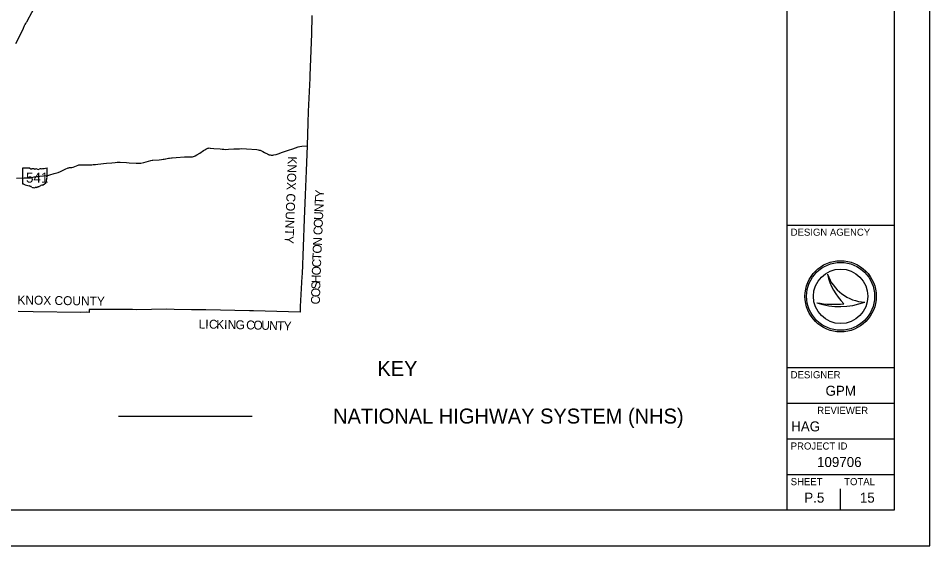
# Model space of a CAD drawing. Extents: x 1851937 to 2123937, y 789467 to 965467.
# Drawn here: x 2021685 to 2123937, y 789467 to 848684 of the extents above; entities that cross this region are included whole.
import ezdxf

# ---------------------------------------------------------------- set-up
doc = ezdxf.new("R2010")
doc.units = 0
for name, color, linetype in [('GM_X_County', 7, 'Continuous'), ('GM_X_County_Text', 7, 'Continuous'), ('GM_X_State_Route', 7, 'Continuous'), ('GM_X_State_Shield', 7, 'Continuous'), ('GM_X_US_Route', 7, 'Continuous'), ('SH_Border', 7, 'Continuous'), ('SH_Cut_Line', 7, 'Continuous'), ('SH_Data', 7, 'Continuous'), ('UT_P_Electric', 7, 'Continuous')]:
    doc.layers.add(name, color=color, linetype=linetype)

msp = doc.modelspace()

# ---------------------------------------------------------------- linework, layer by layer
at = {"layer": 'GM_X_County'}
msp.add_lwpolyline([(2054638, 848994), (2054606, 848369), (2054607, 848277), (2054583, 847562), (2054568, 846927), (2054408, 842255), (2054398, 841945), (2054221, 838228), (2054174, 836926), (2054094, 834355), (2053973, 831537), (2053891, 828875), (2053767, 826144), (2053518, 820007), (2053497, 819709), (2053322, 816320), (2053316, 815692), (2048065, 815838), (2047645, 815846), (2042723, 815938), (2041129, 815964), (2039196, 815994), (2038297, 816009), (2034983, 815969), (2034492, 815973), (2032252, 815993), (2029642, 815987), (2029630, 815668), (2029367, 815674), (2028708, 815664), (2023355, 815717), (2021673, 815746)], dxfattribs=at)
at = {"layer": 'GM_X_State_Route'}
for points in [[(2029952, 832238), (2030108, 832256), (2030346, 832282), (2030597, 832307), (2031592, 832399), (2032180, 832461), (2032572, 832505), (2032800, 832522), (2032958, 832528), (2033117, 832530), (2033841, 832480), (2034136, 832461), (2034924, 832412), (2035163, 832410), (2035426, 832426), (2035761, 832494), (2036549, 832724), (2036702, 832748), (2036773, 832755), (2037484, 832806), (2037755, 832831), (2037951, 832850), (2038057, 832865), (2038195, 832895), (2038244, 832916), (2038536, 832971), (2038663, 832988), (2038861, 833008), (2038943, 833011), (2039387, 833039), (2040347, 833121), (2040792, 833119), (2040992, 833115), (2041217, 833138), (2041356, 833181), (2041442, 833206), (2041535, 833241), (2041735, 833349), (2042051, 833548), (2042460, 833818), (2042620, 833921), (2042711, 833981), (2042802, 834029), (2042869, 834062), (2042946, 834091), (2042980, 834103), (2043026, 834112), (2043117, 834118), (2043221, 834116), (2043634, 834075), (2044325, 834014), (2044549, 833991), (2044751, 833969), (2044931, 833965), (2045285, 833980), (2045854, 834016), (2046037, 834022), (2046308, 834034), (2046496, 834041), (2046698, 834045), (2047274, 834013), (2048444, 833936), (2048591, 833916), (2048718, 833892), (2048815, 833859), (2048914, 833819), (2049105, 833723), (2049296, 833623), (2049459, 833538), (2049642, 833451), (2049753, 833395), (2049838, 833365), (2049936, 833340), (2050041, 833326), (2050246, 833322), (2050341, 833331), (2050634, 833403), (2050835, 833470), (2051332, 833641), (2051649, 833755), (2051987, 833864), (2052501, 834035), (2053071, 834242), (2053272, 834299), (2053515, 834326), (2054095, 834352)], [(2021483, 830726), (2022343, 830751), (2022732, 830765), (2023046, 830784), (2023208, 830800), (2023489, 830872), (2023575, 830891), (2023687, 830908), (2023902, 830930), (2024112, 830941), (2024521, 830974), (2024839, 831012), (2025024, 831043), (2025228, 831086), (2025719, 831239), (2026154, 831378), (2026426, 831471), (2026582, 831537), (2027027, 831764)], [(2027027, 831764), (2027032, 831766), (2027197, 831849), (2027294, 831888), (2027353, 831903), (2027427, 831912), (2027560, 831920), (2027694, 831939), (2027839, 831969), (2028042, 832039), (2028415, 832198), (2028477, 832212), (2028581, 832220), (2028628, 832220), (2028803, 832220)], [(2028803, 832220), (2028974, 832217), (2029145, 832214), (2029319, 832215), (2029475, 832212), (2029785, 832219), (2029952, 832238)]]:
    msp.add_lwpolyline(points, dxfattribs=at)
at = {"layer": 'GM_X_State_Shield'}
for p, q in [((2022147, 831806), (2022147, 830105)), ((2022996, 831836), (2022175, 831836)), ((2024949, 830988), (2024949, 831878)), ((2024949, 830988), (2024949, 830988))]:
    msp.add_line(p, q, dxfattribs=at)
for centre, major_axis, start_param, end_param in [((2022180, 831810), (32.5, 0), 1.7126934, 3.2834897), ((2023191, 832033), (315, 0), 4.042523, 4.731795), ((2023295, 830881), (1130, 0), 1.4047578, 1.6578581), ((2023552, 831819), (90.8, 0), 3.8360951, 5.1854146), ((2023685, 831622), (189, 0), 0.950623, 2.079405), ((2023929, 831892), (227, 0), 4.0815608, 5.1457227), ((2024330, 831316), (598, 0), 1.6990114, 2.1078141), ((2023951, 834155), (2971, 0), 4.8143942, 5.0423688), ((2024918, 831882), (31.2, 0), 6.1411519, 7.9890352), ((2024118, 830502), (743, 0), 5.1017525, 6.4400178), ((2025061, 830616), (211, 0), 2.3877238, 3.2625369), ((2024942, 830923), (48.3, 0), 1.8839779, 3.6710726), ((2024635, 830810), (290, 0), 5.9346948, 6.6959481), ((2024916, 830985), (33.4, 0), 5.05454, 6.4181714), ((2022180, 830102), (32.7, 0), 3.00124, 4.5083009), ((2022185, 830276), (250, 0), 4.6659457, 4.8974612), ((2022236, 830007), (90.1, 0), 0.5192072, 1.6278991), ((2023374, 831536), (2146, 0), 4.1959971, 4.4889607), ((2022734, 829341), (671, 0), 0.8235189, 1.3235874), ((2023460, 829999), (426, 0), 4.0264811, 4.9967352), ((2023706, 829411), (350, 0), 1.495662, 1.9409797), ((2023737, 829871), (227, 0), 4.6910439, 5.5073738), ((2023943, 829707), (63.9, 0), 1.1475842, 2.3151517), ((2023915, 829940), (240, 0), 4.9370686, 5.64225), ((2024431, 829628), (407, 0), 1.6476453, 2.4884337)]:
    msp.add_ellipse(centre, major_axis=major_axis, ratio=0.8, start_param=start_param, end_param=end_param, dxfattribs=at)
at = {"layer": 'GM_X_US_Route'}
msp.add_lwpolyline([(2021421, 845836), (2022068, 847069), (2022278, 847551), (2022403, 847858), (2022439, 847929), (2022474, 847990), (2022532, 848078), (2022629, 848224), (2022689, 848316), (2022742, 848412), (2023222, 849335), (2023604, 850061), (2023662, 850170), (2023711, 850276), (2023758, 850401), (2023790, 850533), (2023809, 850673), (2023817, 850909), (2023831, 851404), (2023837, 851730), (2023865, 853646), (2023864, 853944), (2023857, 854259), (2023844, 854619)], dxfattribs=at)
at = {"layer": 'SH_Border'}
for p, q in [((2107937, 793467), (2107937, 961467)), ((2107937, 825467), (2119937, 825467)), ((2107937, 809467), (2119937, 809467)), ((2107937, 805467), (2119937, 805467)), ((2107937, 801467), (2119937, 801467)), ((2107937, 797467), (2119937, 797467))]:
    msp.add_line(p, q, dxfattribs=at)
msp.add_lwpolyline([(1863937, 961467), (2119937, 961467), (2119937, 793467), (1863937, 793467)], close=True, dxfattribs=at)
at = {"layer": 'SH_Cut_Line'}
msp.add_lwpolyline([(1851937, 789467), (2123937, 789467), (2123937, 965467), (1851937, 965467)], close=True, dxfattribs=at)
at = {"layer": 'SH_Data'}
for p, q in [((2112477, 819944), (2112477, 819944)), ((2113937, 817467), (2113937, 817467)), ((2111275, 816743), (2111275, 816743)), ((2116635, 816815), (2116636, 816815)), ((2113937, 793467), (2113937, 795867)), ((2110937, 794867), (2110937, 794867))]:
    msp.add_line(p, q, dxfattribs=at)
for radius in [4000, 3814, 3814, 3058]:
    msp.add_circle((2113937, 817467), radius, dxfattribs=at)
for centre, radius, start, end in [((2116865, 821448), 4639, 198.92567, 198.93195), ((2118711, 821228), 6365, 191.63793, 191.64215), ((2116865, 821448), 4639, 198.93195, 267.16574), ((2118711, 821228), 6365, 191.64215, 226.09467), ((2113853, 824427), 8105, 251.45764, 290.08324), ((2113121, 826702), 10128, 259.49639, 259.49952), ((2113853, 824427), 8105, 251.45274, 251.45764), ((2113121, 826702), 10128, 259.49952, 276.66723)]:
    msp.add_arc(centre, radius, start, end, dxfattribs=at)
at = {"layer": 'UT_P_Electric'}
msp.add_line((2032926, 804027), (2047926, 804027), dxfattribs=at)

# ---------------------------------------------------------------- texts
at = {"layer": 'GM_X_County_Text'}
for s, rotation, p in [('KNOX COUNTY', 267.71717, (2051952, 833195)), ('Y', 87.57765, (2055969, 828531)), ('T', 87.57747, (2055938, 827783)), ('N', 87.57765, (2055900, 826900)), ('U', 87.57765, (2055863, 826016)), ('C', 87.57735, (2055791, 824319)), ('O', 87.57821, (2055826, 825133)), ('O', 87.58091, (2055704, 822249)), ('N', 87.57873, (2055741, 823132)), ('T', 87.61951, (2055673, 821502)), ('C', 87.73455, (2055641, 820689)), ('O', 87.99332, (2055610, 819806)), ('S', 88.4429, (2055563, 818247)), ('H', 88.14677, (2055581, 818923)), ('O', 88.62214, (2055541, 817364)), ('KNOX COUNTY', 359.20933, (2021587, 816558)), ('C', 88.70029, (2055523, 816550)), ('L', 359.04675, (2041917, 813862)), ('I', 358.96503, (2042663, 813850)), ('C', 358.94354, (2043070, 813842)), ('K', 358.92618, (2043885, 813827)), ('I', 358.92369, (2044767, 813811)), ('N', 358.92127, (2045174, 813803)), ('G', 358.88587, (2046057, 813787)), ('C', 358.71051, (2047244, 813763)), ('O', 358.60959, (2048058, 813745)), ('U', 358.47227, (2048940, 813723)), ('N', 358.42486, (2049822, 813700)), ('T', 358.41862, (2050705, 813676)), ('Y', 358.41862, (2051451, 813655))]:
    msp.add_text(s, height=1000, rotation=rotation, dxfattribs=at).set_placement(p)
at = {"layer": 'GM_X_State_Shield'}
msp.add_text('541', height=1120.7, dxfattribs=at).set_placement((2022560, 830225))
at = {"layer": 'SH_Data'}
for s, height, p in [('DESIGN AGENCY', 800, (2108337, 824267)), ('DESIGNER', 800, (2108337, 808267)), ('GPM', 1120, (2112244, 806307)), ('REVIEWER', 800, (2111312, 804267)), ('HAG', 1120, (2108391, 802307)), ('PROJECT ID', 800, (2108337, 800267)), ('109706', 1120, (2111290, 798307)), ('SHEET', 800, (2108337, 796267)), ('TOTAL', 800, (2114337, 796267)), ('P.5', 1120, (2109863, 794307)), ('15', 1120, (2116095, 794307))]:
    msp.add_text(s, height=height, dxfattribs=at).set_placement(p)
at = {"layer": 'UT_P_Electric'}
for s, p in [('KEY', (2061971, 808535)), ('NATIONAL HIGHWAY SYSTEM (NHS)', (2057006, 803187))]:
    msp.add_text(s, height=1680, dxfattribs=at).set_placement(p)

doc.saveas('drawing.dxf')
